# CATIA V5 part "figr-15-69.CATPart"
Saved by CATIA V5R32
Part number: Part1
Bounding box of the stored display mesh (mm): x -110.541 to 53, y 0 to 2, z -29.652 to 29.652
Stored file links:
  D:\PROJECTS\Project 2022\CATIA V5 6R 2022\Resources\Part Files\c15_catia_v5_6r2022_prt\figr-15-69.CATPart
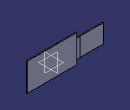
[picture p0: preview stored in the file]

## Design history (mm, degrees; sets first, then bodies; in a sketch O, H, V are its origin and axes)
SheetMetalParameters1: Thickness 2, BendRadius 4, KFactor 0.400515 {= log(min(100,max(20*SheetMetalParameters1.BendRadius,SheetMetalParameters1.Thickness)/SheetMetalParameters1.Thickness))/log(100)/2}, ReliefRadialLength 1, ReliefAxialLength 2, MinimumBendRadius 0
Body1 (main body)
  Sketch1 on zx-plane, origin (0, 0, 0), H (-1, 0, 0), V (0, 0, 1)
    line L1 (53, 29.6521) -> (53, -29.6521)
    line L2 (53, -29.6521) -> (-53, -29.6521)
    line L3 (-53, -29.6521) -> (-53, 29.6521)
    line L4 (-53, 29.6521) -> (53, 29.6521)
    vertical: L1 V, L3 V
    horizontal: L2 H, L4 H
    equidistance: L1 L3 O, L2 L4 O
  Wall1: Thickness 2, Profile Sketch1, OffsetValue 0
  Plane1: type Offset, RefPlane face of Wall1, Offset 10
  Plane2: type Offset, RefPlane face of Wall1, Offset 10
  Flange1: Angle 90, Length 50, Radius 4 {= SheetMetalParameters1.BendRadius}, KFacteur 0.400515 {= log(min(100,max(20*Flange1.Radius,SheetMetalParameters1.Thickness)/SheetMetalParameters1.Thickness))/log(100)/2}, Guide edge [face of Wall1 | face of Wall1], Limit1 Plane1, Limit2 Plane2
  Unfold1: FoldUnfold_Angles 90, FoldUnfold_FoldUnfoldFaces face of Flange1, FoldUnfold_ReferenceFaces face of Wall1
